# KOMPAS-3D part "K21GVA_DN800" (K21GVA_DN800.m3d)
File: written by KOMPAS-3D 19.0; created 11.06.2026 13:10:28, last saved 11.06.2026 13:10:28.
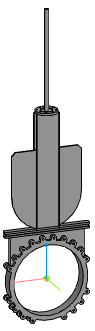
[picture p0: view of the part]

Document properties: Автор: Энергия; Полное имя файла: Z:\3.Личные\kachalov\001_3d для проектировщиков\2.5 Тип_K21GVA. Задвижка\_stp\_stp_K21GVA_DN50-DN1000_с фланцем\K21GVA_DN800.m3d

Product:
- Part/product: K21GVA_DN800

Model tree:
1. Операция без истории:1  (labels: K21GVA_DN800)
